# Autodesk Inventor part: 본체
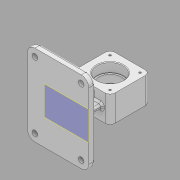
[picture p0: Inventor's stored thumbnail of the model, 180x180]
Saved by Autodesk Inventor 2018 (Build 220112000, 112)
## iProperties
Created: 2020-11
Part Number: 본체
Material: Generic
Document SubType Name: Modeling
Designer: 1-16
Density: 1 g/cm^3
Appearance: Default
Author: 1-16
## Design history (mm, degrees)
sketch "스케치2"
  geometry: L1 (0, 0)-(64, 0); L2 (64, 0)-(64, 64); L3 (64, 64)-(0, 64); L4 (0, 64)-(0, 0)
  constraints: 8 end point, 2 parallel, 1 horizontal, 1 perpendicular
  dimensions: "d0" = 64 distance of L2.end L3.end; "d1" = 64 distance of L1.end L2.end
extrude "돌출1" new body sketch "스케치2" distance "d2" = 42; taper "d3" = 0 deg
sketch "스케치3"
  geometry: L1 (0, 64)-(64, 64) reference; L2 (64, 0)-(0, 0) reference; L3 (64, 64)-(64, 0) reference; C1 r 21 at (32, 32); 2 further points
  constraints: 2 midpoint, 1 centre point, 1 horizontal alignment, 1 vertical alignment
  dimensions: "d4" = 42 diameter of C1
extrude "돌출2" cut sketch "스케치3" distance "d5" = 15; taper "d6" = 0 deg
node "작업 평면1"
sketch "스케치4"
  geometry: L1 (32, -32)-(32, 32) reference; L2 (32, 32)-(-32, 32) reference; C1 r 18 at (0, 0); 2 further points
  constraints: 2 midpoint, 1 centre point, 1 horizontal alignment, 1 vertical alignment
  dimensions: "d7" = 36 diameter of C1
extrude "돌출3" cut sketch "스케치4" extent not by distance; stored distance "d8" = 0; taper "d9" = 0 deg
fillet "모깎기1" dims "d10" = 8
hole "구멍1" diameter "d13" = 3.242; stored, may be unused: countersink angle "d17" = 90 deg, drill point angle "d19" = 118 deg; dims "d11" = 10, "d12" = 10, "d14" = 8, "d15" = 4, "d16" = 2, "d18" = 10
node "작업 평면2"
node "작업 평면3"
node "작업 평면4"
sketch "스케치6"
  geometry: L1 (-38, -44)-(60, -44); L2 (60, -44)-(60, 86); L3 (60, 86)-(-38, 86); L4 (-38, 86)-(-38, -44); L5 (-38, -44)-(60, 86); L6 (60, -44)-(-38, 86); L7 (-8, 42)-(-8, 0) reference; L8 (0, 0)-(0, 42) reference; L9 (48, 0)-(0, 0) reference; L10 (48, 42)-(48, 0) reference; L11 (0, 42)-(48, 42) reference; 3 further points
  constraints: 12 end point, 4 midpoint, 2 parallel, 1 horizontal, 1 horizontal alignment, 1 perpendicular
  dimensions: "d25" = 130 distance of L1.end L2.end; "d26" = 98 distance of L2.end L3.end; "d27" = 30 distance between parallel lines of L7 L4
extrude "돌출4" join sketch "스케치6" distance "d28" = 10; taper "d29" = 0 deg
sketch "스케치8"
  geometry: L1 (44, 17)-(4, 17); L2 (4, 17)-(4, 25); L3 (4, 25)-(44, 25); L4 (44, 25)-(44, 17); L5 (44, 17)-(4, 25); L6 (4, 17)-(44, 25); L7 (-38, 86)-(-38, -44) reference; 4 further points
  constraints: 12 end point, 4 midpoint, 2 parallel, 1 horizontal, 1 horizontal alignment, 1 perpendicular
  dimensions: "d30" = 40 distance between parallel lines of L4 L2; "d32" = 8 distance between parallel lines of L1 L3; "d37" = 62 distance from line of L7 point (24, 21)
extrude "돌출5" join sketch "스케치8" stored distance "d33" = 10; taper "d34" = 0 deg
sketch "스케치9"
  geometry: L1 (20, 4)-(28, 4); L2 (28, 4)-(28, 38); L3 (28, 38)-(20, 38); L4 (20, 38)-(20, 4); L5 (20, 4)-(28, 38); L6 (28, 4)-(20, 38); L7 (60, 86)-(-38, 86) reference; L8 (-38, 86)-(-38, -44) reference; 2 further points
  constraints: 12 end point, 2 midpoint, 2 parallel, 1 horizontal, 1 perpendicular
  dimensions: "d35" = 34 distance between parallel lines of L3 L1; "d36" = 8 distance between parallel lines of L2 L4; "d38" = 65 distance from line of L7 point (24, 21); "d39" = 62 distance from line of L8 point (24, 21)
extrude "돌출6" join sketch "스케치9" stored distance "d40" = 10; taper "d41" = 0 deg
fillet "모깎기2" dims "d42" = 12
hole "구멍2" diameter "d45" = 9; stored, may be unused: countersink angle "d49" = 90 deg, drill point angle "d51" = 118 deg; dims "d43" = 10, "d44" = 10, "d46" = 8, "d47" = 4, "d48" = 2, "d50" = 10
node "작업 평면5"
node "작업 평면6"
fillet "모깎기3" dims "d52" = 3
fillet "모깎기4" dims "d53" = 3
chamfer "모따기1" distance "d54" = 1; stored, may be unused: second distance "d55" = 2, angle "d56" = 45 deg
fillet "모깎기5" dims "d57" = 0.3
sketch "스케치10"
  geometry: L1 (-38, 74)-(-38, -32) reference; L2 (48, 86)-(-26, 86) reference; 2 further points
  constraints: 1 other
  dimensions: "d58" = 10 distance from line of L1 point (-28, 21); "d59" = 65 distance from line of L2 point (-28, 21)
feature "엠보싱1" sketch "스케치10" dims "d0" = 64, "d1" = 64, "d60" = 0.5, "d61" = 0
node "솔리드1"
mirror "미러1"
mirror "미러2"
mirror "미러3"
mirror "미러4"
mirror "미러5"
mirror "미러6"
node "투영된 루프1"
